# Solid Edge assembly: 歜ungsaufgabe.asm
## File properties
Author: Administrator
Template: Normal.asm
Last saved by: Administrator
Revision: 1
Application: Solid Edge
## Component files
Teil1.par
Teil2.par
Teil3.par
Zylinder.par
